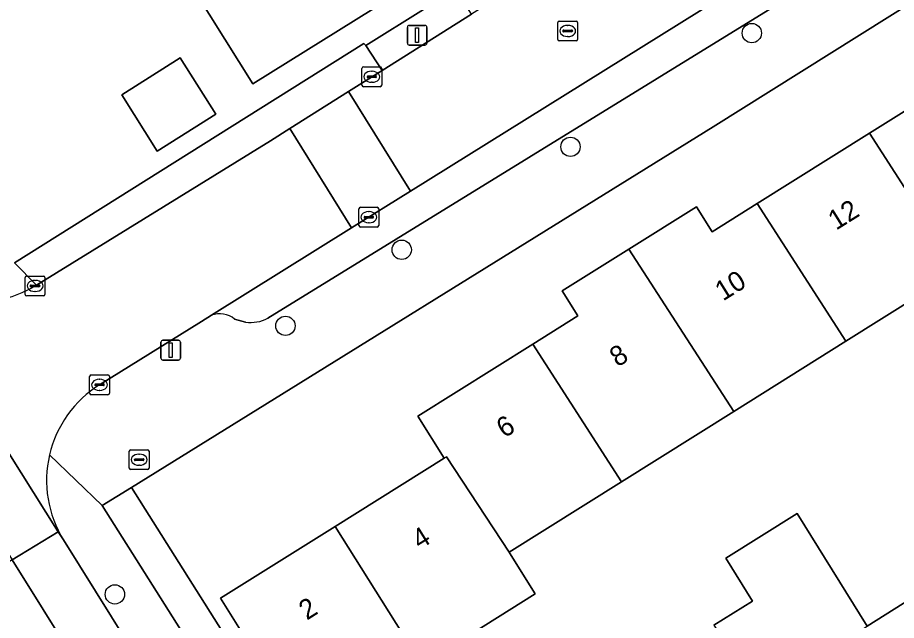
# Model space of a CAD drawing. Extents: x 158455 to 159797, y 387218 to 388672.
# Drawn here: x 158888.19 to 158932.65, y 387860.45 to 387890.92 of the extents above; entities that cross this region are included whole.
import ezdxf

# ---------------------------------------------------------------- set-up
doc = ezdxf.new("R2010")
doc.units = 0
for name, color, linetype in [('IMGEO_Boom', 7, 'Continuous'), ('IMGEO_Brandkraan', 7, 'Continuous'), ('IMGEO_Erf', 7, 'Continuous'), ('IMGEO_Groenvoorziening', 7, 'Continuous'), ('IMGEO_Kolk', 7, 'Continuous'), ('IMGEO_Lichtmast', 7, 'Continuous'), ('IMGEO_Pand', 7, 'Continuous'), ('IMGEO_Pand_nummerreeks', 7, 'Continuous'), ('IMGEO_Parkeervlak_open', 7, 'Continuous'), ('IMGEO_Rijbaan_lokaal_gesloten', 7, 'Continuous'), ('IMGEO_Rijbaan_lokaal_open', 7, 'Continuous'), ('IMGEO_Rioolput', 7, 'Continuous'), ('IMGEO_Voetpad_open', 7, 'Continuous')]:
    doc.layers.add(name, color=color, linetype=linetype)

msp = doc.modelspace()

# ---------------------------------------------------------------- linework, layer by layer
at = {"layer": 'IMGEO_Boom'}
for centre in [(158925.331, 387890.137), (158916.158, 387884.387), (158907.621, 387879.183), (158901.739, 387875.337), (158893.111, 387861.762)]:
    msp.add_circle(centre, 0.489, dxfattribs=at)
at = {"layer": 'IMGEO_Brandkraan'}
for p, q in [((158893.914, 387869.071), (158894.766, 387869.071)), ((158893.839, 387868.145), (158893.839, 387868.997)), ((158894.098, 387868.565), (158894.098, 387868.577)), ((158894.141, 387868.614), (158894.539, 387868.614)), ((158894.327, 387868.851), (158894.352, 387868.851)), ((158894.582, 387868.577), (158894.582, 387868.565)), ((158894.84, 387868.997), (158894.84, 387868.145)), ((158894.536, 387868.528), (158894.138, 387868.528)), ((158894.35, 387868.291), (158894.325, 387868.291)), ((158894.766, 387868.071), (158893.914, 387868.071))]:
    msp.add_line(p, q, dxfattribs=at)
for points in [[(158893.914, 387869.071), (158894.766, 387869.071)], [(158893.839, 387868.145), (158893.839, 387868.997)], [(158894.84, 387868.997), (158894.84, 387868.145)], [(158894.766, 387868.071), (158893.914, 387868.071)]]:
    msp.add_lwpolyline(points, dxfattribs=at)
for centre, radius, start, end in [((158893.916, 387868.995), 0.0765, 91.552, 178.448), ((158893.916, 387868.995), 0.0765, 91.552, 178.448), ((158894.764, 387868.995), 0.0765, 1.552, 88.448), ((158894.764, 387868.995), 0.0765, 1.552, 88.448), ((158894.138, 387868.574), 0.0403, 85.8775, 175.7526), ((158894.543, 387868.576), 0.0386, 1.7309, 96.639), ((158893.916, 387868.147), 0.0765, 181.552, 268.448), ((158893.916, 387868.147), 0.0765, 181.552, 268.448), ((158894.135, 387868.564), 0.0366, 178.938, 274.7102), ((158894.539, 387868.571), 0.043, 264.8664, 352.4533), ((158894.764, 387868.147), 0.0765, 271.552, 358.448), ((158894.764, 387868.147), 0.0765, 271.552, 358.448)]:
    msp.add_arc(centre, radius, start, end, dxfattribs=at)
for centre, major_axis, ratio, start_param, end_param in [((158894.326, 387868.571), (-0.387, 0.002), 0.722429, 4.712389, 7.853982), ((158894.351, 387868.571), (-0.39, 0.002), 0.717154, 1.570796, 4.712389)]:
    msp.add_ellipse(centre, major_axis=major_axis, ratio=ratio, start_param=start_param, end_param=end_param, dxfattribs=at)
at = {"layer": 'IMGEO_Erf'}
for points in [[(158888.037, 387878.531), (158905.701, 387889.612), (158905.813, 387889.502), (158908.73, 387891.329), (158908.541, 387893.968), (158905.754, 387898.587), (158904.814, 387898.068), (158890.622, 387921.112), (158892.352, 387922.241), (158878.009, 387944.836)], [(158887.068, 387919.204), (158889.231, 387920.556), (158892.851, 387914.764), (158896.397, 387909.09), (158899.937, 387903.426), (158903.477, 387897.761), (158907.102, 387891.961), (158900.085, 387887.575), (158896.466, 387893.367), (158892.938, 387899.016), (158889.404, 387904.673), (158885.87, 387910.33)], [(158958.858, 387907.622), (158923.376, 387885.398), (158893.956, 387867.168), (158906.9, 387846.655)], [(158902.841, 387854.568), (158898.459, 387861.57), (158904.249, 387865.193), (158909.773, 387868.65), (158908.442, 387870.777), (158914.246, 387874.409), (158916.533, 387875.84), (158915.738, 387877.11), (158919.114, 387879.22), (158922.53, 387881.356), (158923.323, 387880.089), (158925.606, 387881.518), (158931.285, 387885.072), (158936.955, 387888.621)], [(158935.773, 387878.112), (158930.093, 387874.558), (158924.414, 387871.004), (158918.734, 387867.449), (158913.055, 387863.895), (158913.079, 387863.858), (158914.376, 387861.786), (158908.648, 387858.202)], [(158923.409, 387860.198), (158925.371, 387861.417), (158924.016, 387863.598), (158927.626, 387865.844), (158931.17, 387860.15), (158934.941, 387862.527)]]:
    msp.add_lwpolyline(points, dxfattribs=at)
msp.add_lwpolyline([(158896.409, 387888.887), (158898.209, 387886.04), (158895.254, 387884.172), (158893.454, 387887.019)], close=True, dxfattribs=at)
at = {"layer": 'IMGEO_Groenvoorziening'}
msp.add_lwpolyline([(158906.9, 387846.655), (158893.956, 387867.168), (158892.473, 387866.249), (158905.4, 387845.796)], close=True, dxfattribs=at)
at = {"layer": 'IMGEO_Kolk'}
for p, q in [((158905.609, 387887.502), (158905.609, 387888.354)), ((158905.684, 387888.428), (158906.536, 387888.428)), ((158906.097, 387888.208), (158906.122, 387888.208)), ((158906.61, 387888.354), (158906.61, 387887.502)), ((158905.868, 387887.922), (158905.868, 387887.934)), ((158906.306, 387887.885), (158905.908, 387887.885)), ((158905.911, 387887.971), (158906.309, 387887.971)), ((158906.352, 387887.934), (158906.352, 387887.922)), ((158906.536, 387887.428), (158905.684, 387887.428)), ((158906.12, 387887.648), (158906.095, 387887.648)), ((158905.457, 387880.404), (158905.457, 387881.256)), ((158905.532, 387881.33), (158906.384, 387881.33)), ((158905.945, 387881.11), (158905.97, 387881.11)), ((158906.458, 387881.256), (158906.458, 387880.404)), ((158905.716, 387880.824), (158905.716, 387880.836)), ((158906.154, 387880.787), (158905.756, 387880.787)), ((158905.759, 387880.873), (158906.157, 387880.873)), ((158906.2, 387880.836), (158906.2, 387880.824)), ((158906.384, 387880.33), (158905.532, 387880.33)), ((158905.968, 387880.55), (158905.943, 387880.55)), ((158888.573, 387876.929), (158888.573, 387877.781)), ((158888.648, 387877.855), (158889.5, 387877.855)), ((158889.061, 387877.635), (158889.086, 387877.635)), ((158889.574, 387877.781), (158889.574, 387876.929)), ((158888.832, 387877.349), (158888.832, 387877.361)), ((158889.27, 387877.312), (158888.872, 387877.312)), ((158888.875, 387877.398), (158889.273, 387877.398)), ((158889.084, 387877.075), (158889.059, 387877.075)), ((158889.316, 387877.361), (158889.316, 387877.349)), ((158889.5, 387876.855), (158888.648, 387876.855)), ((158891.834, 387871.93), (158891.834, 387872.782)), ((158891.909, 387872.856), (158892.761, 387872.856)), ((158892.322, 387872.636), (158892.347, 387872.636)), ((158892.835, 387872.782), (158892.835, 387871.93)), ((158892.093, 387872.35), (158892.093, 387872.362)), ((158892.531, 387872.313), (158892.133, 387872.313)), ((158892.136, 387872.399), (158892.534, 387872.399)), ((158892.577, 387872.362), (158892.577, 387872.35)), ((158892.761, 387871.856), (158891.909, 387871.856)), ((158892.345, 387872.076), (158892.32, 387872.076))]:
    msp.add_line(p, q, dxfattribs=at)
for points in [[(158905.609, 387887.502), (158905.609, 387888.354)], [(158905.684, 387888.428), (158906.536, 387888.428)], [(158906.61, 387888.354), (158906.61, 387887.502)], [(158906.536, 387887.428), (158905.684, 387887.428)], [(158905.457, 387880.404), (158905.457, 387881.256)], [(158905.532, 387881.33), (158906.384, 387881.33)], [(158906.458, 387881.256), (158906.458, 387880.404)], [(158906.384, 387880.33), (158905.532, 387880.33)], [(158888.573, 387876.929), (158888.573, 387877.781)], [(158888.648, 387877.855), (158889.5, 387877.855)], [(158889.574, 387877.781), (158889.574, 387876.929)], [(158889.5, 387876.855), (158888.648, 387876.855)], [(158891.834, 387871.93), (158891.834, 387872.782)], [(158891.909, 387872.856), (158892.761, 387872.856)], [(158892.835, 387872.782), (158892.835, 387871.93)], [(158892.761, 387871.856), (158891.909, 387871.856)]]:
    msp.add_lwpolyline(points, dxfattribs=at)
for centre, radius, start, end in [((158905.686, 387888.352), 0.0765, 91.552, 178.448), ((158905.686, 387888.352), 0.0765, 91.552, 178.448), ((158906.534, 387888.352), 0.0765, 1.552, 88.448), ((158906.534, 387888.352), 0.0765, 1.552, 88.448), ((158905.908, 387887.931), 0.0403, 85.8775, 175.7526), ((158905.905, 387887.921), 0.0366, 178.938, 274.7102), ((158906.309, 387887.928), 0.043, 264.8664, 352.4533), ((158906.313, 387887.933), 0.0386, 1.7309, 96.639), ((158905.686, 387887.504), 0.0765, 181.552, 268.448), ((158905.686, 387887.504), 0.0765, 181.552, 268.448), ((158906.534, 387887.504), 0.0765, 271.552, 358.448), ((158906.534, 387887.504), 0.0765, 271.552, 358.448), ((158905.534, 387881.254), 0.0765, 91.552, 178.448), ((158905.534, 387881.254), 0.0765, 91.552, 178.448), ((158906.382, 387881.254), 0.0765, 1.552, 88.448), ((158906.382, 387881.254), 0.0765, 1.552, 88.448), ((158905.756, 387880.833), 0.0403, 85.8775, 175.7526), ((158905.753, 387880.823), 0.0366, 178.938, 274.7102), ((158906.157, 387880.83), 0.043, 264.8664, 352.4533), ((158906.161, 387880.835), 0.0386, 1.7309, 96.639), ((158905.534, 387880.406), 0.0765, 181.552, 268.448), ((158905.534, 387880.406), 0.0765, 181.552, 268.448), ((158906.382, 387880.406), 0.0765, 271.552, 358.448), ((158906.382, 387880.406), 0.0765, 271.552, 358.448), ((158888.65, 387877.779), 0.0765, 91.552, 178.448), ((158888.65, 387877.779), 0.0765, 91.552, 178.448), ((158889.498, 387877.779), 0.0765, 1.552, 88.448), ((158889.498, 387877.779), 0.0765, 1.552, 88.448), ((158888.872, 387877.358), 0.0403, 85.8775, 175.7526), ((158888.869, 387877.348), 0.0366, 178.938, 274.7102), ((158889.273, 387877.355), 0.043, 264.8664, 352.4533), ((158889.277, 387877.36), 0.0386, 1.7309, 96.639), ((158888.65, 387876.931), 0.0765, 181.552, 268.448), ((158888.65, 387876.931), 0.0765, 181.552, 268.448), ((158889.498, 387876.931), 0.0765, 271.552, 358.448), ((158889.498, 387876.931), 0.0765, 271.552, 358.448), ((158891.911, 387872.78), 0.0765, 91.552, 178.448), ((158891.911, 387872.78), 0.0765, 91.552, 178.448), ((158892.759, 387872.78), 0.0765, 1.552, 88.448), ((158892.759, 387872.78), 0.0765, 1.552, 88.448), ((158892.133, 387872.359), 0.0403, 85.8775, 175.7526), ((158892.13, 387872.349), 0.0366, 178.938, 274.7102), ((158892.534, 387872.356), 0.043, 264.8664, 352.4533), ((158892.538, 387872.361), 0.0386, 1.7309, 96.639), ((158891.911, 387871.932), 0.0765, 181.552, 268.448), ((158891.911, 387871.932), 0.0765, 181.552, 268.448), ((158892.759, 387871.932), 0.0765, 271.552, 358.448), ((158892.759, 387871.932), 0.0765, 271.552, 358.448)]:
    msp.add_arc(centre, radius, start, end, dxfattribs=at)
for centre, major_axis, ratio, start_param, end_param in [((158906.096, 387887.928), (-0.387, 0.002), 0.722429, 4.712389, 7.853982), ((158906.121, 387887.928), (-0.39, 0.002), 0.717154, 1.570796, 4.712389), ((158905.944, 387880.83), (-0.387, 0.002), 0.722429, 4.712389, 7.853982), ((158905.969, 387880.83), (-0.39, 0.002), 0.717154, 1.570796, 4.712389), ((158889.06, 387877.355), (-0.387, 0.002), 0.722429, 4.712389, 7.853982), ((158889.085, 387877.355), (-0.39, 0.002), 0.717154, 1.570796, 4.712389), ((158892.321, 387872.356), (-0.387, 0.002), 0.722429, 4.712389, 7.853982), ((158892.346, 387872.356), (-0.39, 0.002), 0.717154, 1.570796, 4.712389)]:
    msp.add_ellipse(centre, major_axis=major_axis, ratio=ratio, start_param=start_param, end_param=end_param, dxfattribs=at)
at = {"layer": 'IMGEO_Lichtmast'}
for p, q in [((158907.905, 387889.628), (158907.905, 387890.428)), ((158907.905, 387890.428), (158907.905, 387889.628)), ((158908.005, 387890.528), (158908.795, 387890.528)), ((158908.795, 387890.528), (158908.005, 387890.528)), ((158908.895, 387890.428), (158908.895, 387889.628)), ((158908.895, 387889.628), (158908.895, 387890.428)), ((158908.795, 387889.528), (158908.005, 387889.528)), ((158908.005, 387889.528), (158908.795, 387889.528)), ((158895.436, 387873.707), (158895.436, 387874.507)), ((158895.436, 387874.507), (158895.436, 387873.707)), ((158895.536, 387874.607), (158896.326, 387874.607)), ((158896.326, 387874.607), (158895.536, 387874.607)), ((158896.426, 387874.507), (158896.426, 387873.707)), ((158896.426, 387873.707), (158896.426, 387874.507)), ((158896.326, 387873.607), (158895.536, 387873.607)), ((158895.536, 387873.607), (158896.326, 387873.607))]:
    msp.add_line(p, q, dxfattribs=at)
for points in [[(158908.325, 387890.403), (158908.475, 387890.403), (158908.475, 387889.653), (158908.325, 387889.653), (158908.325, 387890.403)], [(158895.856, 387874.482), (158896.006, 387874.482), (158896.006, 387873.732), (158895.856, 387873.732), (158895.856, 387874.482)]]:
    msp.add_lwpolyline(points, dxfattribs=at)
for centre, start, end in [((158908.005, 387890.428), 90, 180), ((158908.005, 387890.428), 90, 180), ((158908.795, 387890.428), 0, 90), ((158908.795, 387890.428), 360, 90), ((158908.005, 387889.628), 180, 270), ((158908.005, 387889.628), 180, 270), ((158908.795, 387889.628), 270, 0), ((158908.795, 387889.628), 270, 0), ((158895.536, 387874.507), 90, 180), ((158895.536, 387874.507), 90, 180), ((158896.326, 387874.507), 0, 90), ((158896.326, 387874.507), 360, 90), ((158895.536, 387873.707), 180, 270), ((158895.536, 387873.707), 180, 270), ((158896.326, 387873.707), 270, 0), ((158896.326, 387873.707), 270, 0)]:
    msp.add_arc(centre, 0.1, start, end, dxfattribs=at)
at = {"layer": 'IMGEO_Pand'}
for points in [[(158903.477, 387897.761), (158896.466, 387893.367), (158900.085, 387887.575), (158907.102, 387891.961)], [(158898.209, 387886.04), (158896.409, 387888.887), (158893.454, 387887.019), (158895.254, 387884.172)], [(158931.285, 387885.072), (158935.773, 387878.112), (158941.453, 387881.667), (158936.955, 387888.621)], [(158931.285, 387885.072), (158925.606, 387881.518), (158930.093, 387874.558), (158935.773, 387878.112)], [(158925.606, 387881.518), (158923.323, 387880.089), (158922.53, 387881.356), (158919.114, 387879.22), (158924.414, 387871.004), (158930.093, 387874.558)], [(158919.114, 387879.22), (158915.738, 387877.11), (158916.533, 387875.84), (158914.246, 387874.409), (158918.734, 387867.449), (158924.414, 387871.004)], [(158918.734, 387867.449), (158914.246, 387874.409), (158908.442, 387870.777), (158909.773, 387868.65), (158909.887, 387868.72), (158913.055, 387863.895)], [(158913.079, 387863.858), (158913.055, 387863.895), (158909.887, 387868.72), (158909.773, 387868.65), (158904.249, 387865.193), (158908.648, 387858.202), (158914.376, 387861.786)], [(158923.409, 387860.198), (158926.173, 387855.913), (158928.062, 387857.087), (158927.569, 387857.881), (158931.17, 387860.15), (158927.626, 387865.844), (158924.016, 387863.598), (158925.371, 387861.417)], [(158908.648, 387858.202), (158904.249, 387865.193), (158898.459, 387861.57), (158902.841, 387854.568), (158907.08, 387857.221)]]:
    msp.add_lwpolyline(points, close=True, dxfattribs=at)
at = {"layer": 'IMGEO_Parkeervlak_open'}
for points in [[(158949.967, 387908.21), (158923.719, 387891.905), (158908.07, 387882.149), (158905.083, 387880.287), (158898.003, 387875.873)], [(158900.843, 387875.718), (158940.243, 387899.97), (158948.74, 387905.373)], [(158899.166, 387875.681), (158899.725, 387875.528)]]:
    msp.add_lwpolyline(points, dxfattribs=at)
for centre, radius, start, end in [((158898.407, 387874.701), 1.24, 52.245, 109.0062), ((158899.996, 387877.315), 1.807, 261.3623, 297.9278)]:
    msp.add_arc(centre, radius, start, end, dxfattribs=at)
at = {"layer": 'IMGEO_Rijbaan_lokaal_gesloten'}
msp.add_lwpolyline([(158857.71, 387916.557), (158844.256, 387938.083), (158828.405, 387963.308), (158826.242, 387967.003), (158821.291, 387974.98), (158819.155, 387978.39), (158808.574, 387995.299), (158807.699, 387996.716), (158779.748, 388041.252), (158777.679, 388039.896), (158792.31, 388017.418), (158834.227, 387949.391), (158871.964, 387889.05), (158887.922, 387863.502), (158890.244, 387864.932), (158881.497, 387878.849), (158879.01, 387882.568), (158877.715, 387884.504), (158870.764, 387895.592)], close=True, dxfattribs=at)
for points in [[(158959.591, 387753.588), (158948.358, 387771.822), (158935.188, 387792.904), (158922.531, 387813.295), (158913.231, 387828.204), (158908.724, 387835.428), (158907.553, 387837.293), (158897.714, 387852.97), (158890.508, 387864.512), (158890.244, 387864.932), (158887.922, 387863.502), (158910.852, 387826.792), (158942.469, 387776.24), (158958.617, 387750.353)], [(158958.617, 387750.353), (158942.469, 387776.24), (158910.852, 387826.792), (158887.922, 387863.502), (158885.025, 387861.694), (158886.183, 387859.869), (158892.214, 387850.364), (158894.338, 387846.957), (158900.756, 387836.663), (158907.93, 387825.243), (158911.116, 387820.171), (158923.424, 387800.449), (158934.705, 387782.558), (158940.201, 387773.668), (158950.329, 387757.013)]]:
    msp.add_lwpolyline(points, dxfattribs=at)
at = {"layer": 'IMGEO_Rijbaan_lokaal_open'}
for points in [[(158878.009, 387944.836), (158892.352, 387922.241), (158906.737, 387899.206), (158905.754, 387898.587), (158908.541, 387893.968), (158908.73, 387891.329), (158905.813, 387889.502), (158906.624, 387888.25), (158911.145, 387891.098), (158910.882, 387891.522), (158915.979, 387894.7), (158916.242, 387894.276), (158918.245, 387895.525), (158917.455, 387896.962), (158916.437, 387896.322), (158913.459, 387897.023), (158901.833, 387915.478), (158903.55, 387916.493), (158901.845, 387919.208), (158906.177, 387921.929), (158905.268, 387923.321), (158897.893, 387934.619), (158899.452, 387935.658), (158885.25, 387958.082)], [(158972.153, 387929.247), (158959.618, 387921.443), (158956.159, 387919.289), (158955.409, 387918.822), (158952.985, 387917.313), (158952.175, 387916.803), (158948.536, 387914.511), (158945.477, 387912.585), (158943.867, 387911.571), (158940.641, 387909.54), (158932.263, 387904.264), (158918.245, 387895.525), (158916.242, 387894.276), (158911.145, 387891.098), (158906.624, 387888.25), (158904.931, 387887.184), (158908.07, 387882.149), (158923.719, 387891.905), (158949.967, 387908.21), (158950.141, 387908.318), (158951.711, 387909.397)], [(158905.083, 387880.287), (158901.953, 387885.308), (158900.98, 387884.695), (158889.152, 387877.401)], [(158892.337, 387872.359), (158897.487, 387875.551), (158898.003, 387875.873), (158905.083, 387880.287)], [(158881.497, 387878.849), (158890.244, 387864.932), (158890.508, 387864.512)], [(158934.941, 387862.527), (158931.17, 387860.15)]]:
    msp.add_lwpolyline(points, dxfattribs=at)
msp.add_lwpolyline([(158908.07, 387882.149), (158904.931, 387887.184), (158901.953, 387885.308), (158905.083, 387880.287)], close=True, dxfattribs=at)
for centre, radius, start, end in [((158886.119, 387882.323), 5.781, 216.9301, 301.6472), ((158895.363, 387867.518), 5.708, 122.0078, 166.8924), ((158895.365, 387867.516), 5.711, 166.8769, 211.7409)]:
    msp.add_arc(centre, radius, start, end, dxfattribs=at)
at = {"layer": 'IMGEO_Rioolput'}
for p, q in [((158915.516, 387889.817), (158915.516, 387890.669)), ((158915.591, 387890.743), (158916.443, 387890.743)), ((158916.004, 387890.523), (158916.029, 387890.523)), ((158916.517, 387890.669), (158916.517, 387889.817)), ((158915.775, 387890.237), (158915.775, 387890.249)), ((158916.213, 387890.2), (158915.815, 387890.2)), ((158915.818, 387890.286), (158916.216, 387890.286)), ((158916.027, 387889.963), (158916.002, 387889.963)), ((158916.259, 387890.249), (158916.259, 387890.237)), ((158916.443, 387889.743), (158915.591, 387889.743))]:
    msp.add_line(p, q, dxfattribs=at)
for points in [[(158915.516, 387889.817), (158915.516, 387890.669)], [(158915.591, 387890.743), (158916.443, 387890.743)], [(158916.517, 387890.669), (158916.517, 387889.817)], [(158916.443, 387889.743), (158915.591, 387889.743)]]:
    msp.add_lwpolyline(points, dxfattribs=at)
for centre, radius, start, end in [((158915.593, 387890.667), 0.0765, 91.552, 178.448), ((158915.593, 387890.667), 0.0765, 91.552, 178.448), ((158916.441, 387890.667), 0.0765, 1.552, 88.448), ((158916.441, 387890.667), 0.0765, 1.552, 88.448), ((158915.815, 387890.246), 0.0403, 85.8775, 175.7526), ((158915.812, 387890.236), 0.0366, 178.938, 274.7102), ((158916.216, 387890.243), 0.043, 264.8664, 352.4533), ((158916.22, 387890.248), 0.0386, 1.7309, 96.639), ((158915.593, 387889.819), 0.0765, 181.552, 268.448), ((158915.593, 387889.819), 0.0765, 181.552, 268.448), ((158916.441, 387889.819), 0.0765, 271.552, 358.448), ((158916.441, 387889.819), 0.0765, 271.552, 358.448)]:
    msp.add_arc(centre, radius, start, end, dxfattribs=at)
for centre, major_axis, ratio, start_param, end_param in [((158916.003, 387890.243), (-0.387, 0.002), 0.722429, 4.712389, 7.853982), ((158916.028, 387890.243), (-0.39, 0.002), 0.717154, 1.570796, 4.712389)]:
    msp.add_ellipse(centre, major_axis=major_axis, ratio=ratio, start_param=start_param, end_param=end_param, dxfattribs=at)
at = {"layer": 'IMGEO_Voetpad_open'}
for points in [[(158923.376, 387885.398), (158958.858, 387907.622), (158959.711, 387908.139)], [(158948.74, 387905.373), (158940.243, 387899.97), (158900.843, 387875.718)], [(158889.803, 387868.813), (158892.473, 387866.249), (158893.956, 387867.168), (158923.376, 387885.398)], [(158889.152, 387877.401), (158888.037, 387878.531)], [(158898.003, 387875.873), (158897.487, 387875.551), (158892.337, 387872.359)], [(158899.725, 387875.528), (158899.166, 387875.681)], [(158927.158, 387814.532), (158926.411, 387813.992), (158923.849, 387818.108), (158924.603, 387818.533), (158917.204, 387830.423), (158912.63, 387837.774), (158912.549, 387837.724), (158911.099, 387840.073), (158911.171, 387840.117), (158911.055, 387840.304), (158909.277, 387843.075), (158906.9, 387846.655), (158905.4, 387845.796), (158892.473, 387866.249), (158889.803, 387868.813)], [(158890.508, 387864.512), (158897.714, 387852.97), (158907.553, 387837.293)]]:
    msp.add_lwpolyline(points, dxfattribs=at)
msp.add_lwpolyline([(158900.98, 387884.695), (158901.953, 387885.308), (158904.931, 387887.184), (158906.624, 387888.25), (158905.813, 387889.502), (158905.701, 387889.612), (158888.037, 387878.531), (158889.152, 387877.401)], close=True, dxfattribs=at)
for centre, radius, start, end in [((158886.119, 387882.323), 5.781, 216.9301, 301.6472), ((158898.407, 387874.701), 1.24, 52.245, 109.0062), ((158899.996, 387877.315), 1.807, 261.3623, 297.9278), ((158895.363, 387867.518), 5.708, 122.0078, 166.8924), ((158895.365, 387867.516), 5.711, 166.8769, 211.7409)]:
    msp.add_arc(centre, radius, start, end, dxfattribs=at)

# ---------------------------------------------------------------- texts
at = {"layer": 'IMGEO_Pand_nummerreeks'}
for s, rotation, p in [('12', 32.0385, (158929.595, 387880.145)), ('10', 32.0398, (158923.874, 387876.566)), ('8', 32.0398, (158918.54, 387873.227)), ('6', 32.0398, (158912.812, 387869.642)), ('4', 32.0341, (158908.537, 387864.006)), ('2', 32.0324, (158902.82, 387860.43))]:
    msp.add_text(s, height=1, rotation=rotation, dxfattribs=at).set_placement(p)

doc.saveas('drawing.dxf')
